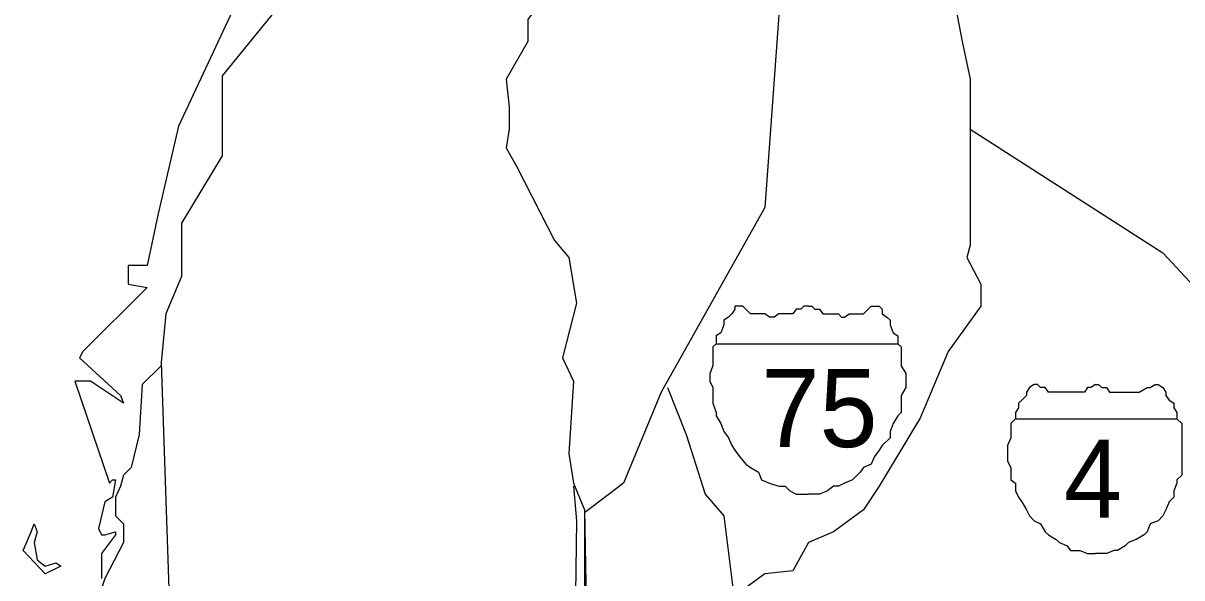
# Model space of a CAD drawing. Extents: x -827.9 to -798.1, y -2199.1 to -2182.2.
# Drawn here: x -806.3742 to -806.0075, y -2184.6119 to -2184.4362 of the extents above; entities that cross this region are included whole.
import ezdxf

# ---------------------------------------------------------------- set-up
doc = ezdxf.new("R2010")
doc.units = 0
for name, color, linetype in [('FLMap1', 7, 'Continuous'), ('FLMap2', 7, 'Continuous'), ('FLMap3', 7, 'Continuous'), ('TextMisc', 7, 'Continuous')]:
    doc.layers.add(name, color=color, linetype=linetype)

msp = doc.modelspace()

# ---------------------------------------------------------------- linework, layer by layer
at = {"layer": 'FLMap1'}
for p, q in [((-806.15489, -2184.53773), (-806.09734, -2184.53773)), ((-806.06013, -2184.56154), (-806.00903, -2184.56154))]:
    msp.add_line(p, q, dxfattribs=at)
for points in [[(-806.12562, -2184.52582), (-806.12711, -2184.52582), (-806.1281, -2184.52682), (-806.12959, -2184.52682), (-806.13058, -2184.5283), (-806.13157, -2184.5283), (-806.13306, -2184.5283), (-806.13505, -2184.5283), (-806.13653, -2184.5293), (-806.13802, -2184.5293), (-806.13951, -2184.5283), (-806.1405, -2184.5283), (-806.1415, -2184.5283), (-806.14398, -2184.5283), (-806.14546, -2184.52682), (-806.14646, -2184.52582), (-806.14894, -2184.52582), (-806.14894, -2184.52682), (-806.14993, -2184.5283), (-806.15092, -2184.5293), (-806.15241, -2184.53029), (-806.15241, -2184.53178), (-806.1534, -2184.53426), (-806.15489, -2184.53525), (-806.15489, -2184.53773), (-806.15588, -2184.53872), (-806.15588, -2184.5422), (-806.15588, -2184.54468), (-806.15688, -2184.54716), (-806.15688, -2184.54964), (-806.15588, -2184.55162), (-806.15588, -2184.5541), (-806.15588, -2184.55658), (-806.15489, -2184.55956), (-806.15489, -2184.56055), (-806.1534, -2184.56303), (-806.15241, -2184.56551), (-806.15092, -2184.5675), (-806.14993, -2184.56998), (-806.14894, -2184.57147), (-806.14745, -2184.57345), (-806.14546, -2184.57593), (-806.14398, -2184.57692), (-806.1415, -2184.57841), (-806.1405, -2184.58089), (-806.13802, -2184.58189), (-806.13505, -2184.58288), (-806.13306, -2184.58288), (-806.13157, -2184.58437), (-806.12959, -2184.58536), (-806.12562, -2184.58536)], [(-806.12562, -2184.52582), (-806.12463, -2184.52582), (-806.12364, -2184.52682), (-806.12215, -2184.52682), (-806.12115, -2184.5283), (-806.11967, -2184.5283), (-806.11768, -2184.5283), (-806.11619, -2184.5283), (-806.1152, -2184.5293), (-806.11421, -2184.5293), (-806.11272, -2184.5283), (-806.11173, -2184.5283), (-806.11024, -2184.5283), (-806.10826, -2184.5283), (-806.10677, -2184.52682), (-806.10577, -2184.52582), (-806.10329, -2184.52582), (-806.1023, -2184.52682), (-806.1023, -2184.5283), (-806.10081, -2184.5293), (-806.09982, -2184.53029), (-806.09982, -2184.53178), (-806.09883, -2184.53426), (-806.09734, -2184.53525), (-806.09734, -2184.53773), (-806.09635, -2184.53872), (-806.09635, -2184.5422), (-806.09635, -2184.54468), (-806.09486, -2184.54716), (-806.09486, -2184.54964), (-806.09486, -2184.55162), (-806.09635, -2184.5541), (-806.09635, -2184.55658), (-806.09635, -2184.55956), (-806.09734, -2184.56055), (-806.09883, -2184.56303), (-806.09982, -2184.56551), (-806.09982, -2184.5675), (-806.1023, -2184.56998), (-806.10329, -2184.57147), (-806.10478, -2184.57345), (-806.10577, -2184.57593), (-806.10826, -2184.57692), (-806.10925, -2184.57841), (-806.11173, -2184.58089), (-806.11421, -2184.58189), (-806.11619, -2184.58288), (-806.11768, -2184.58288), (-806.11967, -2184.58437), (-806.12215, -2184.58536), (-806.12562, -2184.58536)], [(-806.03483, -2184.55063), (-806.03483, -2184.55063), (-806.03632, -2184.55162), (-806.03731, -2184.55162), (-806.0383, -2184.55311), (-806.03979, -2184.55311), (-806.04078, -2184.55311), (-806.04277, -2184.55311), (-806.04475, -2184.55311), (-806.04475, -2184.55311), (-806.04723, -2184.55311), (-806.04723, -2184.55311), (-806.04971, -2184.55311), (-806.05071, -2184.55162), (-806.05219, -2184.55162), (-806.05319, -2184.55063), (-806.05418, -2184.55063), (-806.05567, -2184.55162), (-806.05666, -2184.55311), (-806.05666, -2184.5541), (-806.05815, -2184.55559), (-806.05914, -2184.55658), (-806.05914, -2184.55807), (-806.06013, -2184.55956), (-806.06013, -2184.56154), (-806.06162, -2184.56303), (-806.06162, -2184.56551), (-806.06162, -2184.5675), (-806.06261, -2184.56998), (-806.06261, -2184.57246), (-806.06261, -2184.57494), (-806.06162, -2184.57692), (-806.06162, -2184.5794), (-806.06162, -2184.58089), (-806.06013, -2184.58189), (-806.06013, -2184.58437), (-806.05914, -2184.58635), (-806.05815, -2184.58784), (-806.05666, -2184.59032), (-806.05567, -2184.5923), (-806.05418, -2184.59379), (-806.05219, -2184.59478), (-806.05071, -2184.59727), (-806.04971, -2184.59826), (-806.04723, -2184.59975), (-806.04624, -2184.60074), (-806.04376, -2184.60173), (-806.04277, -2184.60322), (-806.03979, -2184.60322), (-806.03731, -2184.60421), (-806.03483, -2184.60421)], [(-806.03483, -2184.55063), (-806.03384, -2184.55063), (-806.03284, -2184.55162), (-806.03136, -2184.55162), (-806.03036, -2184.55311), (-806.02888, -2184.55311), (-806.02788, -2184.55311), (-806.02689, -2184.55311), (-806.0254, -2184.55311), (-806.02441, -2184.55311), (-806.02292, -2184.55311), (-806.02193, -2184.55311), (-806.02094, -2184.55311), (-806.01846, -2184.55162), (-806.01746, -2184.55162), (-806.01598, -2184.55063), (-806.01498, -2184.55063), (-806.0135, -2184.55162), (-806.0125, -2184.55311), (-806.0125, -2184.5541), (-806.01151, -2184.55559), (-806.01002, -2184.55658), (-806.01002, -2184.55807), (-806.00903, -2184.55956), (-806.00903, -2184.56154), (-806.00754, -2184.56303), (-806.00754, -2184.56551), (-806.00754, -2184.5675), (-806.00754, -2184.56998), (-806.00754, -2184.57246), (-806.00754, -2184.57494), (-806.00754, -2184.57692), (-806.00754, -2184.5794), (-806.00903, -2184.58089), (-806.00903, -2184.58189), (-806.01002, -2184.58437), (-806.01002, -2184.58635), (-806.01151, -2184.58784), (-806.0125, -2184.59032), (-806.0135, -2184.5923), (-806.01498, -2184.59379), (-806.01746, -2184.59478), (-806.01846, -2184.59727), (-806.01945, -2184.59826), (-806.02193, -2184.59975), (-806.02441, -2184.60074), (-806.0254, -2184.60173), (-806.02788, -2184.60322), (-806.02888, -2184.60322), (-806.03136, -2184.60421), (-806.03483, -2184.60421)]]:
    msp.add_lwpolyline(points, dxfattribs=at)
at = {"layer": 'FLMap2'}
for points in [[(-806.13653, -2184.28917), (-806.13653, -2184.29264), (-806.16084, -2184.33333), (-806.16184, -2184.34424), (-806.16283, -2184.34871), (-806.17126, -2184.3502), (-806.20252, -2184.4137), (-806.20946, -2184.42809), (-806.21443, -2184.43503), (-806.21443, -2184.44198), (-806.22137, -2184.45389), (-806.22038, -2184.46282), (-806.22038, -2184.46976), (-806.22137, -2184.47571), (-806.2179, -2184.48167), (-806.20599, -2184.50499), (-806.20153, -2184.51044), (-806.19905, -2184.52483), (-806.20351, -2184.5422), (-806.20004, -2184.54964), (-806.20153, -2184.57246), (-806.20004, -2184.58189), (-806.19657, -2184.59032)], [(-806.24221, -2184.30009), (-806.24221, -2184.30009), (-806.2432, -2184.32638), (-806.25164, -2184.36607), (-806.2561, -2184.37202), (-806.26106, -2184.37748), (-806.27743, -2184.39782), (-806.28984, -2184.4266), (-806.31117, -2184.45289), (-806.31117, -2184.4782), (-806.32407, -2184.49953), (-806.32407, -2184.50052), (-806.32407, -2184.5164), (-806.32903, -2184.5283), (-806.33052, -2184.54368)], [(-806.29083, -2184.34176), (-806.29827, -2184.39435), (-806.29926, -2184.4137), (-806.32506, -2184.46877), (-806.33151, -2184.49705), (-806.33498, -2184.51292), (-806.34094, -2184.51292), (-806.34094, -2184.51888), (-806.33498, -2184.51987), (-806.35533, -2184.54021), (-806.35632, -2184.5422), (-806.34342, -2184.5541), (-806.34243, -2184.55658), (-806.35284, -2184.54964), (-806.35781, -2184.54964), (-806.34689, -2184.58189)], [(-806.07898, -2184.43156), (-806.077, -2184.44198), (-806.07452, -2184.45389), (-806.07452, -2184.50647), (-806.07551, -2184.51044), (-806.07105, -2184.51888), (-806.07105, -2184.52582), (-806.08146, -2184.54021), (-806.0904, -2184.56154), (-806.09139, -2184.56303), (-806.10329, -2184.58288)], [(-806.07452, -2184.46976), (-806.0135, -2184.50896), (-805.99365, -2184.53029), (-805.99067, -2184.53525), (-805.98819, -2184.5412), (-805.97877, -2184.55162), (-805.97777, -2184.55311), (-805.97678, -2184.59131)], [(-806.33052, -2184.54368), (-806.32754, -2184.631), (-806.32407, -2184.63696), (-806.32308, -2184.69153), (-806.30174, -2184.72775), (-806.30026, -2184.77637)], [(-806.33052, -2184.54468), (-806.33647, -2184.55063), (-806.33747, -2184.56651), (-806.33995, -2184.57692), (-806.34243, -2184.5794), (-806.34342, -2184.58288), (-806.34491, -2184.58635), (-806.34491, -2184.5923), (-806.34243, -2184.59478), (-806.34243, -2184.60074), (-806.34838, -2184.61215), (-806.35185, -2184.62257), (-806.35284, -2184.63299), (-806.35632, -2184.65482), (-806.35632, -2184.67168), (-806.35533, -2184.67367), (-806.35533, -2184.68458), (-806.35185, -2184.68458), (-806.35036, -2184.73717), (-806.33895, -2184.73965), (-806.32407, -2184.74908), (-806.31712, -2184.759), (-806.30026, -2184.759)], [(-806.34689, -2184.58189), (-806.3459, -2184.58089), (-806.34491, -2184.58089), (-806.3459, -2184.58635), (-806.34838, -2184.58784), (-806.35036, -2184.59627), (-806.34937, -2184.59826), (-806.34838, -2184.59826), (-806.34491, -2184.59727), (-806.34491, -2184.59826), (-806.34937, -2184.60421), (-806.34937, -2184.61215)], [(-806.20004, -2184.58288), (-806.19905, -2184.59379), (-806.20004, -2184.66325), (-806.19905, -2184.66821)], [(-806.10329, -2184.58288), (-806.10826, -2184.59032), (-806.11768, -2184.59727), (-806.12562, -2184.60074), (-806.13058, -2184.60967), (-806.13951, -2184.61066), (-806.14894, -2184.61761), (-806.14894, -2184.62604), (-806.15489, -2184.65234), (-806.1534, -2184.65829), (-806.15092, -2184.66573), (-806.14894, -2184.68706), (-806.14298, -2184.69748), (-806.13951, -2184.70294), (-806.13951, -2184.72626), (-806.14298, -2184.74511), (-806.14298, -2184.79175), (-806.14894, -2184.81258), (-806.16531, -2184.82697)], [(-806.19657, -2184.59032), (-806.19557, -2184.64291)], [(-806.37418, -2184.60322), (-806.3717, -2184.59727), (-806.37071, -2184.59478), (-806.36971, -2184.59727), (-806.37071, -2184.60074), (-806.36971, -2184.6062), (-806.36723, -2184.60818), (-806.36376, -2184.60719), (-806.36376, -2184.60719), (-806.36227, -2184.60818), (-806.36723, -2184.61066), (-806.37418, -2184.60322)]]:
    msp.add_lwpolyline(points, dxfattribs=at)
at = {"layer": 'FLMap3'}
for points in [[(-806.10826, -2183.89029), (-806.09486, -2183.91509), (-806.07799, -2183.9781), (-806.07551, -2184.01432), (-806.07551, -2184.07286), (-806.06609, -2184.09469), (-806.05815, -2184.11801), (-806.04475, -2184.14331), (-806.04277, -2184.16117), (-806.03384, -2184.17606), (-806.03036, -2184.2341), (-806.0383, -2184.24601), (-806.06609, -2184.30554), (-806.07898, -2184.31795), (-806.08742, -2184.33581), (-806.09635, -2184.34275), (-806.10478, -2184.3884), (-806.11619, -2184.39882), (-806.11867, -2184.41221), (-806.13505, -2184.43354), (-806.13951, -2184.49457)], [(-806.13951, -2184.49457), (-806.17226, -2184.55311), (-806.18416, -2184.58189), (-806.19657, -2184.59131), (-806.19657, -2184.6573)], [(-806.17027, -2184.55162), (-806.16432, -2184.56651), (-806.15836, -2184.58536), (-806.15241, -2184.5923), (-806.14894, -2184.62009), (-806.1405, -2184.62951), (-806.13951, -2184.66226), (-806.14298, -2184.68458), (-806.14894, -2184.69748), (-806.14894, -2184.72278), (-806.15092, -2184.73469), (-806.15092, -2184.7466), (-806.15588, -2184.76099), (-806.16432, -2184.77537), (-806.16531, -2184.79075), (-806.17821, -2184.80316), (-806.19061, -2184.82102), (-806.19409, -2184.82548), (-806.19756, -2184.82796), (-806.20946, -2184.83987), (-806.22484, -2184.85674), (-806.22633, -2184.85773)]]:
    msp.add_lwpolyline(points, dxfattribs=at)

# ---------------------------------------------------------------- texts
at = {"layer": 'TextMisc'}
for s, height, p in [('75', 0.024695, (-806.14052, -2184.57047)), ('4', 0.0247, (-806.04481, -2184.5928))]:
    msp.add_text(s, height=height, dxfattribs=at).set_placement(p)

doc.saveas('drawing.dxf')
